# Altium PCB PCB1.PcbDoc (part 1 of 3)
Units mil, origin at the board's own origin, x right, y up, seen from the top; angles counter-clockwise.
Board outline 5995.03 x 3870.03 mil, 2 copper layers (Top Layer, Bottom Layer); 16 components, 23 nets, 121 pads, 0 vias.
Unrouted connection lines stored in the file: 7.
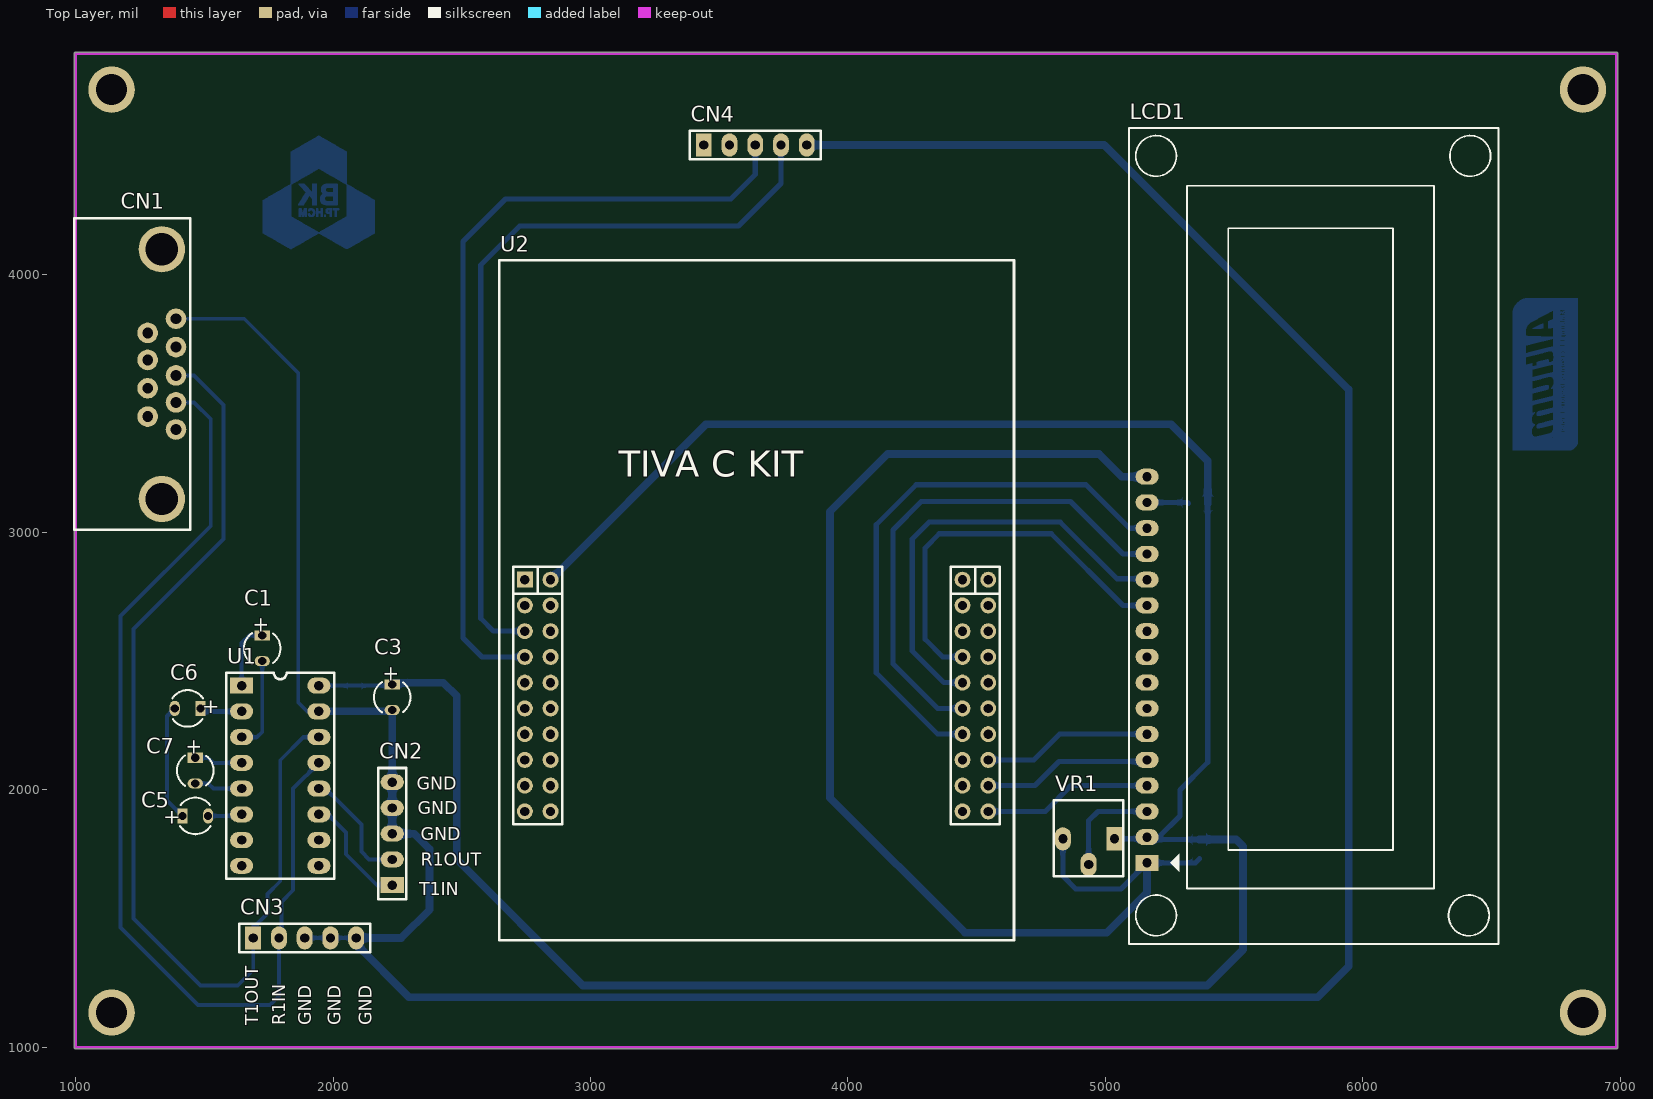
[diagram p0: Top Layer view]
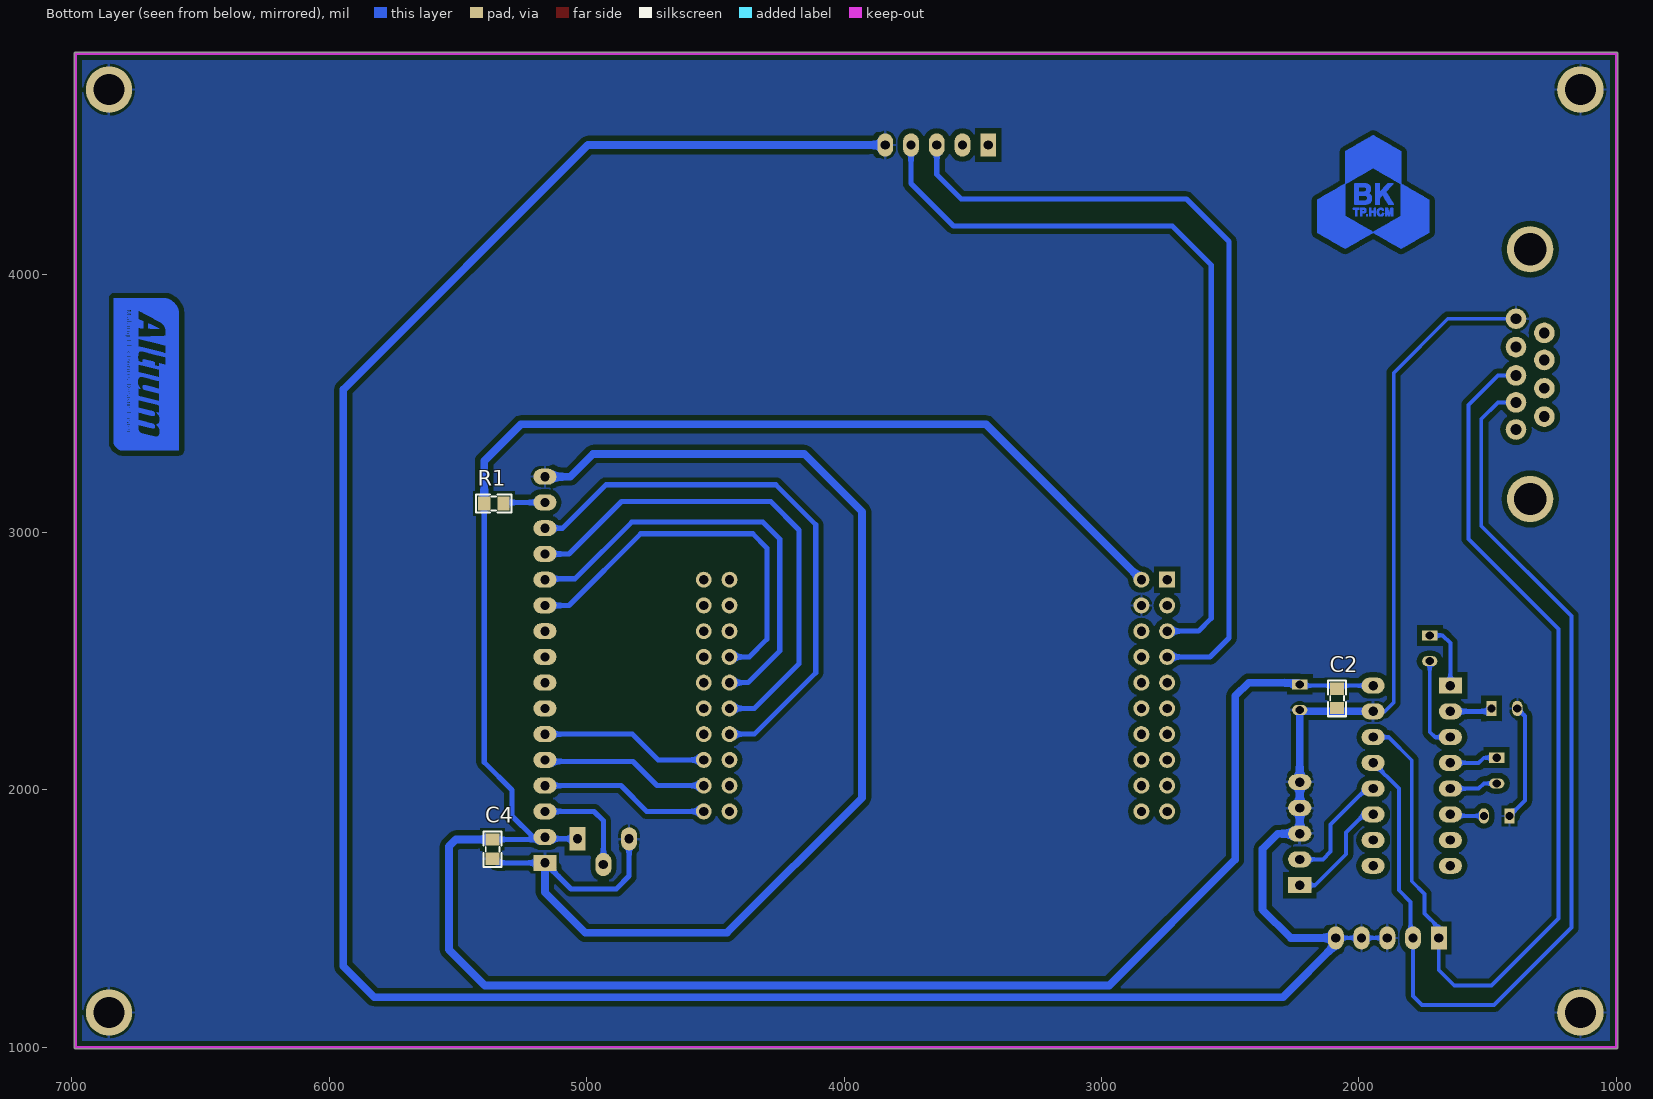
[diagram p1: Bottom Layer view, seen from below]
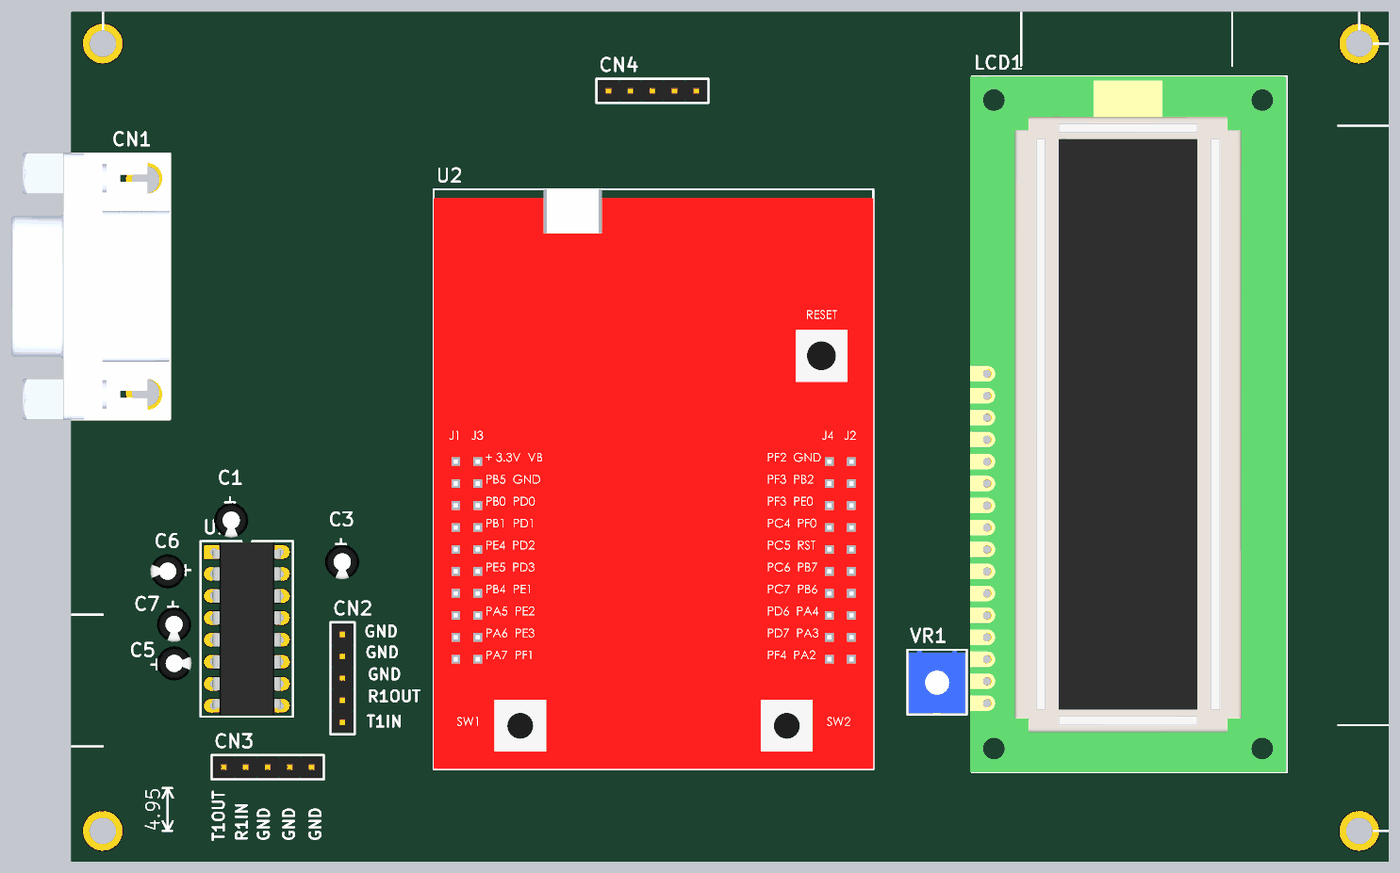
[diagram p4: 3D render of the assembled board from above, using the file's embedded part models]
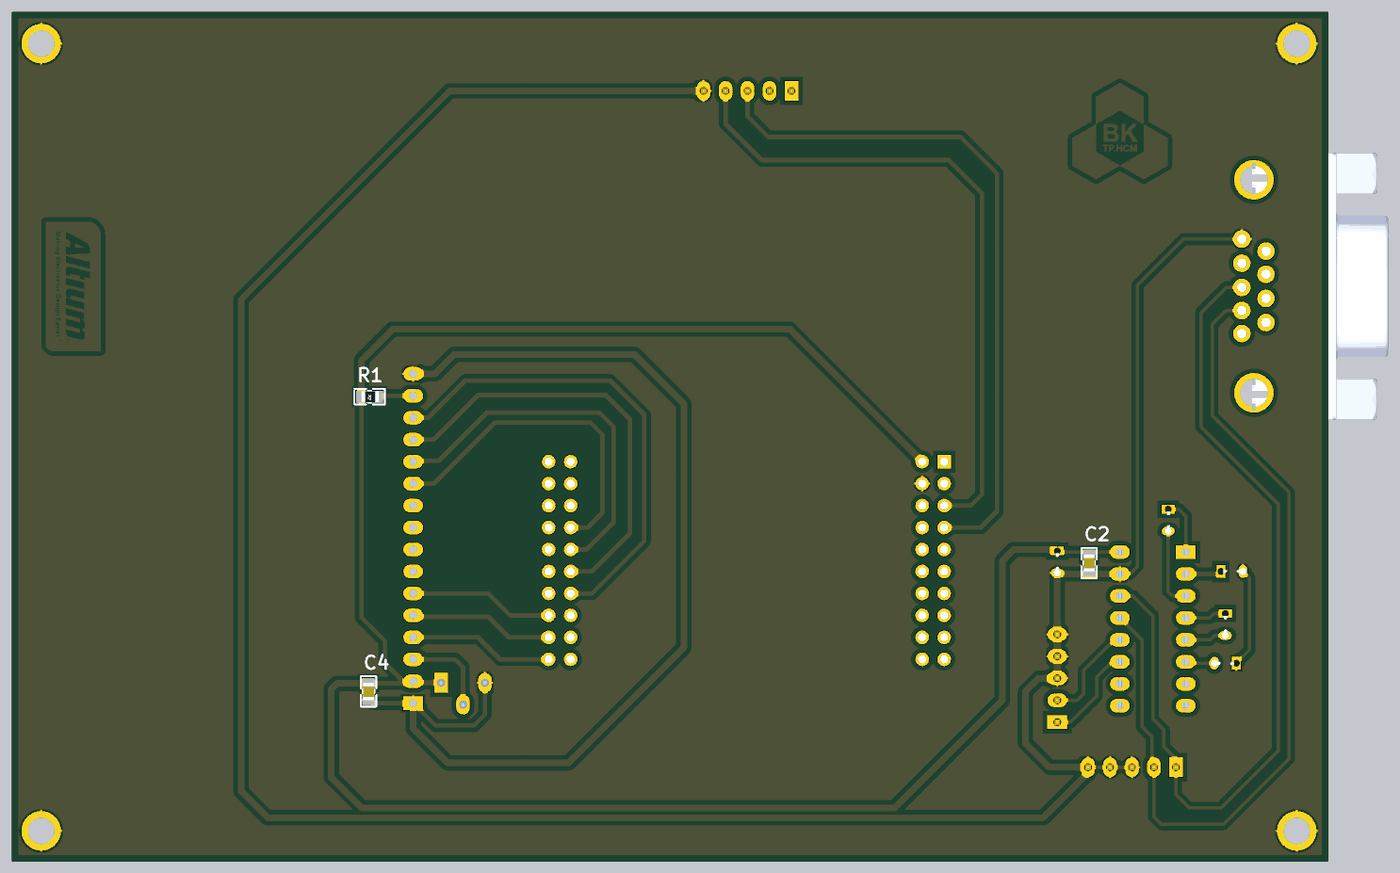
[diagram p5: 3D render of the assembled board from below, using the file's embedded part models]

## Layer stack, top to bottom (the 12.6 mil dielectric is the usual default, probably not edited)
Top Solder: solder mask 0.4, Solder Resist, Dk 3.5
Top Layer: signal copper 1.4
Dielectric 1: dielectric 12.6, FR-4, Dk 4.8
Bottom Layer: signal copper 1.4
Bottom Solder: solder mask 0.4, Solder Resist, Dk 3.5

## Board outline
1000,994.99 cw(c1000,1000) 994.99,1000 994.99,4860 cw(c1000,4860) 1000,4865.02 6985,4865.02 cw(c6985,4860) 6990.02,4860 6990.02,1000 cw(c6985,1000) 6985,994.99

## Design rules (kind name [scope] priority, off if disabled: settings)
Clearance [All] p1: gap=20 ignorepadtopadclearanceinfootprint=FALSE
PolygonConnect [All] p1: connectstyle=Relief reliefconductorwidth=10 reliefentries=4 polygonreliefangle="90 Angle" airgapwidth=10
RoutingVias [All] p1: holewidth=28 width=50 viastyle="Through Hole" minholewidth=28 minwidth=50 maxholewidth=28 maxwidth=50
SolderMaskExpansion [All] p1: expansion=4
Width [All] p1: maxlimit=30 minlimit=15 preferedwidth=20
30 further rules are at their usual default settings.

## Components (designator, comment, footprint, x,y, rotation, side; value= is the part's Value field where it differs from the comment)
C1 "1uF" "TU HOA 3MM" 1725,2550 r270 top value=8-Jun-2000
C2 "104" "tu 0805" 2085,2355 r90 bottom
C3 "1uF" "TU HOA 3MM" 2230,2360 r270 top value=8-Jun-2000
C4 "104" "tu 0805" 5365,1770 r270 bottom
C5 "1uF" "TU HOA 3MM" 1465,1898.79 r0 top value=8-Jun-2000
C6 "1uF" "TU HOA 3MM" 1434.99,2316.5 r180 top value=8-Jun-2000
C7 "1uF" "TU HOA 3MM" 1465,2075 r270 top value=8-Jun-2000
CN1 "DB9 Terminal" DB9 1390,3980 r270 top
CN2 "Header 5p" "HEADER 5P MALE" 2230,1630 r180 top
CN3 "Header 5p" "HEADER 5P MALE" 1690,1425 r90 top
CN4 "Header 5p" "HEADER 5P MALE" 3440,4505 r90 top
LCD1 "CD1602 Xanh Dương" LCD16X2 5162.01,1716.5 r90 top
R1 "1k" "tro smd 0805" 5360,3110 r0 bottom
U1 "MAX232" DIP16 1645,2405 r0 top
U2 "Tiva C LaunchPad Evaluation" "Tiva C LaunchPad Kit" 2745,2816.5 r0 top
VR1 "100K" "VRES TOP" 5034.99,1810 r180 top

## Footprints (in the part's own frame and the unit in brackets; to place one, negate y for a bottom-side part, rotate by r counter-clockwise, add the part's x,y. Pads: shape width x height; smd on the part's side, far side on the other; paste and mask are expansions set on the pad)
DB9 [mil]
  round 80 hole 42: 1(580,0) 2(475,0) 3(370,0) 4(260,0) 5(150,0) 6(530,-110) 7(420,-110) 8(310,-110) 9(205,-110)
  round 180 hole 125: ""(-120,-55) ""(850,-55)
  silkscreen extent -240,-395 970,55, body extent -241,-665 971,55, height 547
DIP16 [mil]
  rect 90x62 hole 36: 1(0,0)
  oval 90x62 hole 36: 2(0,-100) 3(0,-200) 4(0,-300) 5(0,-400) 6(0,-500) 7(0,-600) 8(0,-700) 9(300,-700) 10(300,-600) 11(300,-500) 12(300,-400) 13(300,-300) 14(300,-200) 15(300,-100) 16(300,0)
  silkscreen extent -60,-750 360,50, body extent -6,-743 306,43, height 179
"HEADER 5P MALE" [mil]
  rect 90x62 hole 36: 1(0,0)
  oval 90x62 hole 36: 2(0,-100) 3(0,-200) 4(0,-300) 5(0,-400)
  silkscreen extent -55,-455 55,55, body extent -50,-450 50,50, height 350
LCD16X2 [mil] "LCD dipslay 16x2, 16 pin"
  rect 62x90 hole 36: 1(0,0)
  oval 62x90 hole 36: 2(100,0) 3(200,0) 4(300,0) 5(400,0) 6(500,0) 7(600,0) 8(700,0) 9(800,0) 10(900,0) 11(1000,0) 12(1100,0) 13(1200,0) 14(1300,0) 15(1400,0) 16(1500,0)
  silkscreen extent -315,-1365 2855,70, body extent -315,-1360 2855,77, height 914
"Tiva C LaunchPad Kit" [mil]
  rect 62x62 hole 36: 1(0,0)
  round 62 hole 36: 2(0,-100) 3(0,-200) 4(0,-300) 5(0,-400) 6(0,-500) 7(0,-600) 8(0,-700) 9(0,-800) 10(0,-900) 11(100,0) 12(100,-100) 13(100,-200) 14(100,-300) 15(100,-400) 16(100,-500) 17(100,-600) 18(100,-700) 19(100,-800) 20(100,-900) 21(1700,0) 22(1700,-100) 23(1700,-200) 24(1700,-300) 25(1700,-400) 26(1700,-500) 27(1700,-600) 28(1700,-700) 29(1700,-800) 30(1700,-900) 31(1800,0) 32(1800,-100) 33(1800,-200) 34(1800,-300) 35(1800,-400) 36(1800,-500) 37(1800,-600) 38(1800,-700) 39(1800,-800) 40(1800,-900)
  silkscreen extent -100,-1400 1900,1240, body extent -100,-1400 1900,1240, height 743
"tro smd 0805" [mm]
  rect 1.2x1.4 smd: 1(-0.946,-0.061) 2(0.954,-0.061)
  silkscreen extent -1.75,-0.97 1.75,0.84, body extent -1.56,-0.76 1.44,0.64, height 0.53
"tu 0805" [mm] "Compoment SMD 80x50mil"
  rect 1.2x1.4 smd: 1(-0.946,-0.003) 2(0.954,-0.003)
  silkscreen extent -1.75,-0.89 1.75,0.89, body extent -1.01,-0.64 1.01,0.63, height 0.61
"TU HOA 3MM" [mm]
  rect 1x1.5 hole 0.8: 1(-1.27,0)
  oval 1x1.5 hole 0.8: 2(1.27,0)
  silkscreen extent -1.5,-1.81 1.5,1.8, body extent -2,-2.03 1.99,1.97, height 7.01
"VRES TOP" [mil]
  rect 62x90 hole 36: 1(0,0)
  oval 62x90 hole 36: 2(100,100) 3(200,0)
  silkscreen extent -35,-150 235,145, body extent -30,-146 230,138, height 185

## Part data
C1 C3 C5 C6 C7: library part "Tu 3mm", "C?m"
C2 C4: library part "Tu 0805 104 50V 10%", "Dán"
LCD1: library part LCD16x2A, "C?m"
R1: library part "Tro 0805 1% 1k", "Dán"
U2: "Kit Tiva C LaunchPad Evaluation. Kit is using TM4C123GH6PM MCU"
VR1: library part "Varrible Res"

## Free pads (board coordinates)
  round 180 hole 120: ""(1140,1135) ""(1140,4720) ""(6855,1135) ""(6855,4720)

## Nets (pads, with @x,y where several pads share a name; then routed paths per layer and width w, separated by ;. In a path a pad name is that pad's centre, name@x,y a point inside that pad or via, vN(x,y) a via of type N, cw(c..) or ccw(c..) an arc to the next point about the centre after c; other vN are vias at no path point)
+5: C2.2 C3.1 C4.1 LCD1.2 R1.2 U1.16 U2.11 VR1.1 | length 9876.8
  Bottom Layer w15: U1.16@1945,2405 2225,2405 C3.1@2230,2410
  Bottom Layer w20: VR1.1@5034.99,1810 5155.51,1810 LCD1.2@5162.01,1816.5 ; C4.1@5365.13,1807.23 5171.28,1807.23 LCD1.2@5162.01,1816.5 ; R1.2@5397.57,3112.39 5397.57,2107.43 5290,1999.85 5290,1898.79 5207.71,1816.5 LCD1.2@5162.01,1816.5
  Bottom Layer w30: C3.1@2230,2410 2236.5,2416.5 2428.5,2416.5 2480,2365 2480,1730 2970,1240 5395,1240 5535,1380 5535,1780 5507.77,1807.23 C4.1@5365.13,1807.23 ; U2.11@2845,2816.5 3448.5,3420 5255,3420 5397.57,3277.43 R1.2@5397.57,3112.39
D4: LCD1.11 U2.24 | length 1528.5
  Bottom Layer w20: U2.24@4445,2516.5 4368.5,2516.5 4300,2585 4300,2940 4355,2995 4790,2995 5068.5,2716.5 LCD1.11@5162.01,2716.5
D5: LCD1.12 U2.25 | length 1712.7
  Bottom Layer w20: U2.25@4445,2416.5 4373.5,2416.5 4250,2540 4250,2975 4315,3040 4825,3040 5045,2820 5158.51,2820 LCD1.12@5162.01,2816.5
D6: LCD1.13 U2.26 | length 1978.7
  Bottom Layer w20: U2.26@4445,2316.5 4348.5,2316.5 4175,2490 4175,3010 4285,3120 4865,3120 5068.5,2916.5 LCD1.13@5162.01,2916.5
D7: LCD1.14 U2.27 | length 2194.8
  Bottom Layer w20: U2.27@4445,2216.5 4348.5,2216.5 4110,2455 4110,3030 4265,3185 4925,3185 5093.5,3016.5 LCD1.14@5162.01,3016.5
E: LCD1.6 U2.38 | length 658.4
  Bottom Layer w20: U2.38@4545,2116.5 4721.5,2116.5 4821.5,2216.5 LCD1.6@5162.01,2216.5
GND: C2.1 C3.2 C4.2 C5.1 C6.2 CN1.5 CN2.3 CN2.4 CN2.5 CN3.3 CN3.4 CN3.5 CN4.5 LCD1.1 LCD1.16 pad. U1.15 U2.12 VR1.3 | length 17710.8
  Bottom Layer w15: C6.2@1384.99,2316.5 1355,2286.51 1355,1958.79 C5.1@1415,1898.79 ; CN1.5@1390,3830 1655,3830 1865,3620 1865,2340 1900,2305 U1.15@1945,2305 ; CN3.3@1890,1425 CN3.4@1990,1425 CN3.5@2090,1425
  Bottom Layer w20: VR1.3@4834.99,1810 4834.99,1665.01 4885,1615 5060.51,1615 LCD1.1@5162.01,1716.5 5349.21,1716.5 C4.2@5365.13,1732.43
  Bottom Layer w30: U1.15@1945,2305 2225,2305 C3.2@2230,2310 CN2.5@2230,2030 CN2.4@2230,1930 CN2.3@2230,1830 2315,1830 2375,1770 2375,1535 2265,1425 CN3.5@2090,1425 2090,1400 2295,1195 5825,1195 5945,1315 5945,3555 4995,4505 CN4.5@3840,4505 ; LCD1.16@5162.01,3216.5 5063.5,3216.5 4975,3305 4155,3305 3930,3080 3930,1970 4455,1445 5005,1445 5162.01,1602.01 LCD1.1@5162.01,1716.5 LCD1.1@5175,1703.51
NetC1_1: C1.1 U1.1 | length 257.4
  Bottom Layer w15: U1.1@1645,2405 1645,2570 1675,2600 C1.1@1725,2600
NetC1_2: C1.2 U1.3 | length 363.3
  Bottom Layer w15: U1.3@1645,2205 1705,2205 1725,2225 C1.2@1725,2500
NetC5_2: C5.2 U1.6 | length 132.6
  Bottom Layer w15: C5.2@1515,1898.79 1638.79,1898.79 U1.6@1645,1905
NetC6_1: C6.1 U1.2 | length 164.8
  Bottom Layer w20: C6.1@1484.99,2316.5 1496.49,2305 U1.2@1645,2305
NetC7_1: C7.1 U1.4 | length 188.3
  Bottom Layer w15: C7.1@1465,2125 1515,2125 1535,2105 U1.4@1645,2105
NetC7_2: C7.2 U1.5 | length 188.3
  Bottom Layer w15: C7.2@1465,2025 1515,2025 1535,2005 U1.5@1645,2005
NetLCD1_3: LCD1.3 VR1.2 | length 412.1
  Bottom Layer w20: VR1.2@4934.99,1710 4934.99,1879.99 4971.5,1916.5 LCD1.3@5162.01,1916.5
NetLCD1_15: LCD1.15 R1.1 | length 162.5
  Bottom Layer w20: LCD1.15@5162.01,3116.5 5318.67,3116.5 R1.1@5322.77,3112.39
R1IN: CN1.2 CN3.2 U1.13 | length 4004.9
  Bottom Layer w15: CN1.2@1390,3505 1460,3505 1525,3440 1525,3025 1175,2675 1175,1465 1475,1165 1755,1165 1790,1200 CN3.2@1790,1425 1800,1435 1800,1565 1845,1610 1845,2005 U1.13@1945,2105
R1OUT: CN2.2 U1.12 | length 460.4
  Bottom Layer w15: U1.12@1945,2005 1970,2005 2110,1865 2110,1760 2140,1730 CN2.2@2230,1730
RS: LCD1.4 U2.40 | length 658.4
  Bottom Layer w20: U2.40@4545,1916.5 4766.5,1916.5 4866.5,2016.5 LCD1.4@5162.01,2016.5
RW: LCD1.5 U2.39 | length 658.4
  Bottom Layer w20: U2.39@4545,2016.5 4726.5,2016.5 4820,2110 5155.51,2110 LCD1.5@5162.01,2116.5
Rx: CN4.4 U2.3 | length 3011.8
  Bottom Layer w20: U2.3@2745,2616.5 2623.5,2616.5 2573.5,2666.5 2573.5,4038.5 2725,4190 3575,4190 3740,4355 CN4.4@3740,4505
T1IN: CN2.1 U1.11 | length 448.7
  Bottom Layer w15: U1.11@1945,1905 1980,1905 2050,1835 2050,1750 2170,1630 CN2.1@2230,1630
T1OUT: CN1.3 CN3.1 U1.14 | length 3970.9
  Bottom Layer w15: CN1.3@1390,3610 1460,3610 1575,3495 1575,2975 1225,2625 1225,1500 1485,1240 1630,1240 1690,1300 CN3.1@1690,1425 1690,1465 1745,1520 1745,1595 1795,1645 1795,2115 1885,2205 U1.14@1900,2205
Tx: CN4.3 U2.4 | length 3168.1
  Bottom Layer w20: U2.4@2745,2516.5 2578.5,2516.5 2505,2590 2505,4130 2670,4295 3545,4295 3640,4390 CN4.3@3640,4505
pads on no net: CN1. CN1.1 CN1.4 CN1.6 CN1.7 CN1.8 CN1.9 CN4.1 CN4.2 LCD1.7 LCD1.8 LCD1.9 LCD1.10 U1.7 U1.8 U1.9 U1.10 U2.1 U2.2 U2.5 U2.6 U2.7 U2.8 U2.9 U2.10 U2.13 U2.14 U2.15 U2.16 U2.17 U2.18 U2.19 U2.20 U2.21 U2.22 U2.23 U2.28 U2.29 U2.30 U2.31 U2.32 U2.33 U2.34 U2.35 U2.36 U2.37
copper on no net: | length 205733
